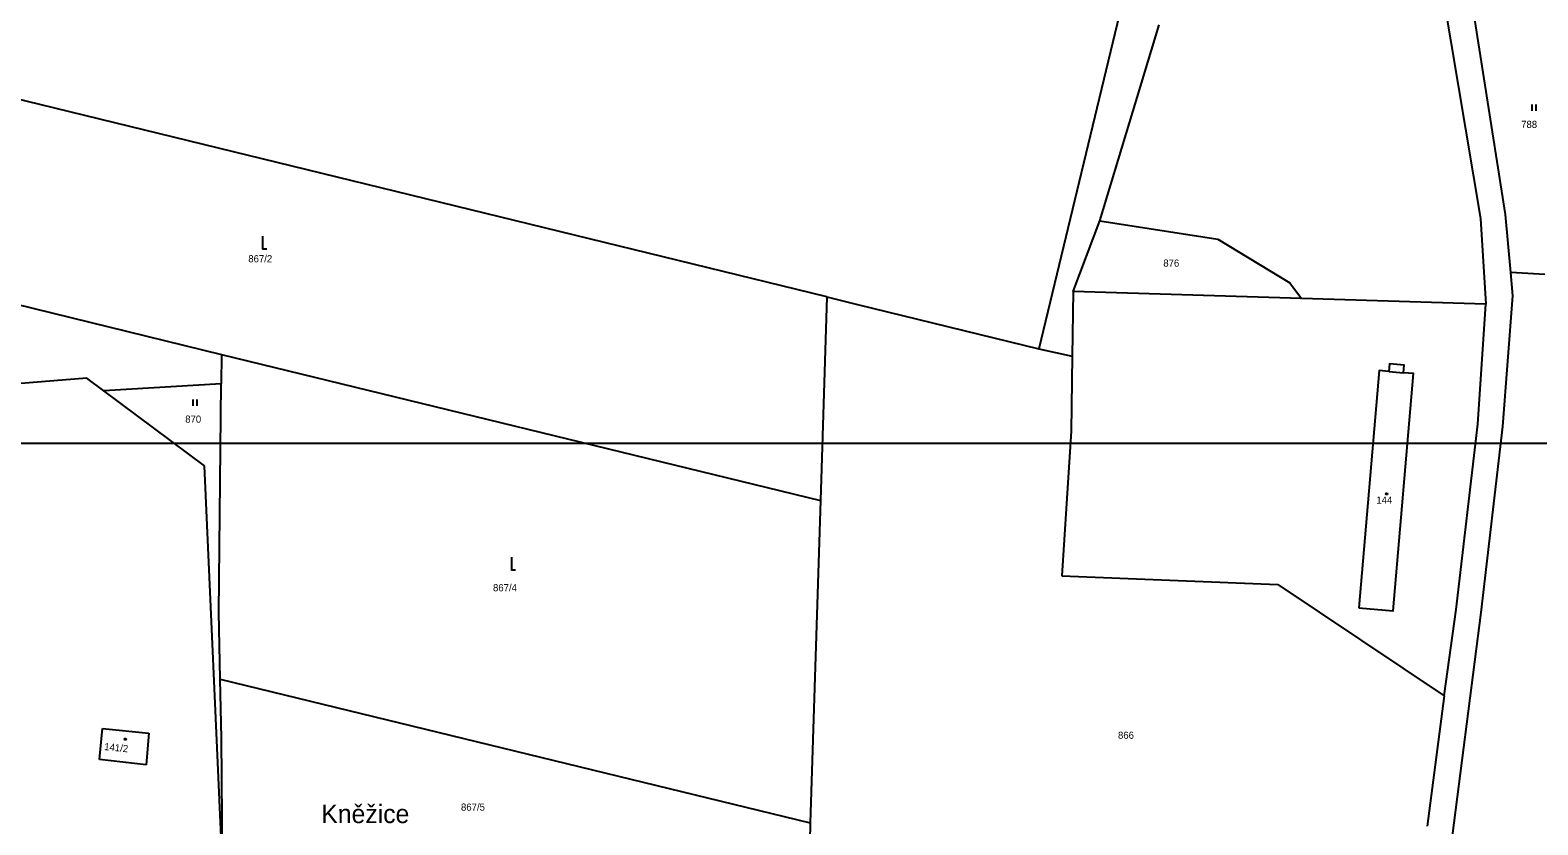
# Model space of a CAD drawing. Extents: x -812394 to -807601, y -1013097 to -1009266.
# Drawn here: x -809776.7 to -809418.3, y -1010590.6 to -1010401.8 of the extents above; entities that cross this region are included whole.
import ezdxf

# ---------------------------------------------------------------- set-up
doc = ezdxf.new("R2010")
doc.units = 0
for name, color, linetype in [('Default', 7, 'Continuous'), ('KLADY_ZMVM', 7, 'Continuous'), ('KN_HRANICE', 7, 'Continuous'), ('KN_KULTURY', 7, 'Continuous'), ('KN_PARCELY', 7, 'Continuous'), ('KN_SLUCKY', 7, 'Continuous')]:
    doc.layers.add(name, color=color, linetype=linetype)

# ---------------------------------------------------------------- blocks, each defined once
blk = doc.blocks.new('302')
at = {"layer": 'Default'}
blk.add_lwpolyline([(0, 3), (0, 0), (1, 0)], dxfattribs=at)
blk = doc.blocks.new('306')
at = {"layer": 'Default'}
for p, q in [((-0.5, 1.5), (-0.5, 0)), ((0.5, 0), (0.5, 1.5))]:
    blk.add_line(p, q, dxfattribs=at)
blk = doc.blocks.new('402')
at = {"layer": 'Default'}
blk.add_lwpolyline([(0.09, 0.15), (0.18, 0), (0.09, -0.15), (-0.09, -0.15), (-0.18, 0), (-0.09, 0.15), (0.09, 0.15)], dxfattribs=at)

msp = doc.modelspace()

# ---------------------------------------------------------------- linework, layer by layer
at = {"layer": 'KLADY_ZMVM'}
msp.add_lwpolyline([(-810000, -1011000), (-810000, -1010500), (-809375, -1010500), (-809375, -1011000), (-809466.04, -1011000)], dxfattribs=at)
at = {"layer": 'KN_HRANICE'}
for p, q in [((-809450.65, -1010334.75), (-809431.9, -1010446.55)), ((-809425.97, -1010445.61), (-809436.85, -1010376.65)), ((-809514.24, -1010383.44), (-809536.89, -1010477.53)), ((-809714.42, -1010434.16), (-809841.57, -1010403.09)), ((-809522.42, -1010447.11), (-809508.32, -1010400.6)), ((-809587.27, -1010465.23), (-809714.42, -1010434.16)), ((-809431.9, -1010446.55), (-809430.67, -1010466.91)), ((-809424.72, -1010459.4), (-809425.97, -1010445.61)), ((-809528.75, -1010463.9), (-809522.42, -1010447.11)), ((-809522.42, -1010447.11), (-809494.36, -1010451.5)), ((-809839.82, -1010452.31), (-809731.16, -1010478.93)), ((-809494.36, -1010451.5), (-809477.25, -1010461.87)), ((-809416.64, -1010459.93), (-809424.72, -1010459.4)), ((-809424.21, -1010464.95), (-809424.72, -1010459.4)), ((-809528.75, -1010463.9), (-809528.97, -1010479.27)), ((-809474.49, -1010465.57), (-809528.75, -1010463.9)), ((-809477.25, -1010461.87), (-809474.49, -1010465.57)), ((-809587.27, -1010465.23), (-809588.81, -1010513.56)), ((-809587.27, -1010465.23), (-809580, -1010467)), ((-809580, -1010467), (-809536.89, -1010477.53)), ((-809430.67, -1010466.91), (-809474.49, -1010465.57)), ((-809426.59, -1010496.04), (-809424.21, -1010464.95)), ((-809731.16, -1010478.93), (-809731.23, -1010485.87)), ((-809731.16, -1010478.93), (-809588.81, -1010513.56)), ((-809536.89, -1010477.53), (-809528.97, -1010479.27)), ((-809528.97, -1010479.27), (-809529.22, -1010497.13)), ((-809763.21, -1010484.53), (-809830.46, -1010490)), ((-809759.15, -1010487.55), (-809763.21, -1010484.53)), ((-809731.23, -1010485.87), (-809759.15, -1010487.55)), ((-809731.8, -1010540.09), (-809731.23, -1010485.87)), ((-809735.22, -1010505.35), (-809759.15, -1010487.55)), ((-809431.77, -1010540.21), (-809426.59, -1010496.04)), ((-809529.22, -1010497.13), (-809531.43, -1010531.51)), ((-809730.9, -1010600.87), (-809735.22, -1010505.35)), ((-809588.81, -1010513.56), (-809591.24, -1010590.16)), ((-809531.43, -1010531.51), (-809480.06, -1010533.57)), ((-809480.06, -1010533.57), (-809440.59, -1010560.03)), ((-809731.49, -1010556.03), (-809731.8, -1010540.09)), ((-809445.19, -1010645.2), (-809431.77, -1010540.21)), ((-809731.22, -1010570.09), (-809731.49, -1010556.03)), ((-809731.49, -1010556.03), (-809591.24, -1010590.16)), ((-809440.59, -1010560.03), (-809444.6, -1010590.99)), ((-809760.19, -1010575.15), (-809759.48, -1010567.72)), ((-809759.48, -1010567.72), (-809748.44, -1010568.84)), ((-809748.44, -1010568.84), (-809749.12, -1010576.39)), ((-809730.9, -1010600.87), (-809731.22, -1010570.09)), ((-809749.12, -1010576.39), (-809760.19, -1010575.15)), ((-809591.24, -1010590.16), (-809591.38, -1010594.61))]:
    msp.add_line(p, q, dxfattribs=at)
msp.add_lwpolyline([(-809440.59, -1010560.03), (-809437.72, -1010539.45), (-809432.57, -1010495.49), (-809430.67, -1010466.91)], dxfattribs=at)
at = {"layer": 'KN_SLUCKY'}
msp.add_line((-809453.74, -1010482.93), (-809450.22, -1010483.22), dxfattribs=at)
for points in [[(-809450.22, -1010483.22), (-809450.07, -1010481.4), (-809453.59, -1010481.09), (-809453.74, -1010482.93)], [(-809453.74, -1010482.93), (-809456, -1010482.74), (-809460.85, -1010539.12)], [(-809460.85, -1010539.12), (-809452.7, -1010539.8), (-809447.88, -1010483.41), (-809450.22, -1010483.22)]]:
    msp.add_lwpolyline(points, dxfattribs=at)

# ---------------------------------------------------------------- block references
at = {"layer": 'KN_KULTURY'}
for name, p in [('306', (-809419.22, -1010421.03)), ('302', (-809721.44, -1010453.78)), ('306', (-809737.47, -1010491.07)), ('402', (-809454.22, -1010512)), ('302', (-809662.28, -1010530.06)), ('402', (-809754.04, -1010570.3))]:
    msp.add_blockref(name, p, dxfattribs=at)

# ---------------------------------------------------------------- texts
at = {"layer": 'KN_PARCELY'}
for s, height, p in [('788', 1.7, (-809422.26, -1010425.08)), ('867/2', 1.7, (-809724.82, -1010456.99)), ('876', 1.7, (-809507.32, -1010458.03)), ('870', 1.7, (-809739.81, -1010495.1)), ('144', 1.7, (-809456.68, -1010514.34)), ('867/4', 1.7, (-809666.65, -1010535.16)), ('866', 1.7, (-809518.09, -1010570.21)), ('Kněžice', 4.4, (-809707.47, -1010590.23)), ('867/5', 1.7, (-809674.26, -1010587.28))]:
    msp.add_text(s, height=height, dxfattribs=at).set_placement(p)
msp.add_text('141/2', height=1.7, rotation=354.374, dxfattribs=at).set_placement((-809759.12, -1010572.87))

doc.saveas('drawing.dxf')
